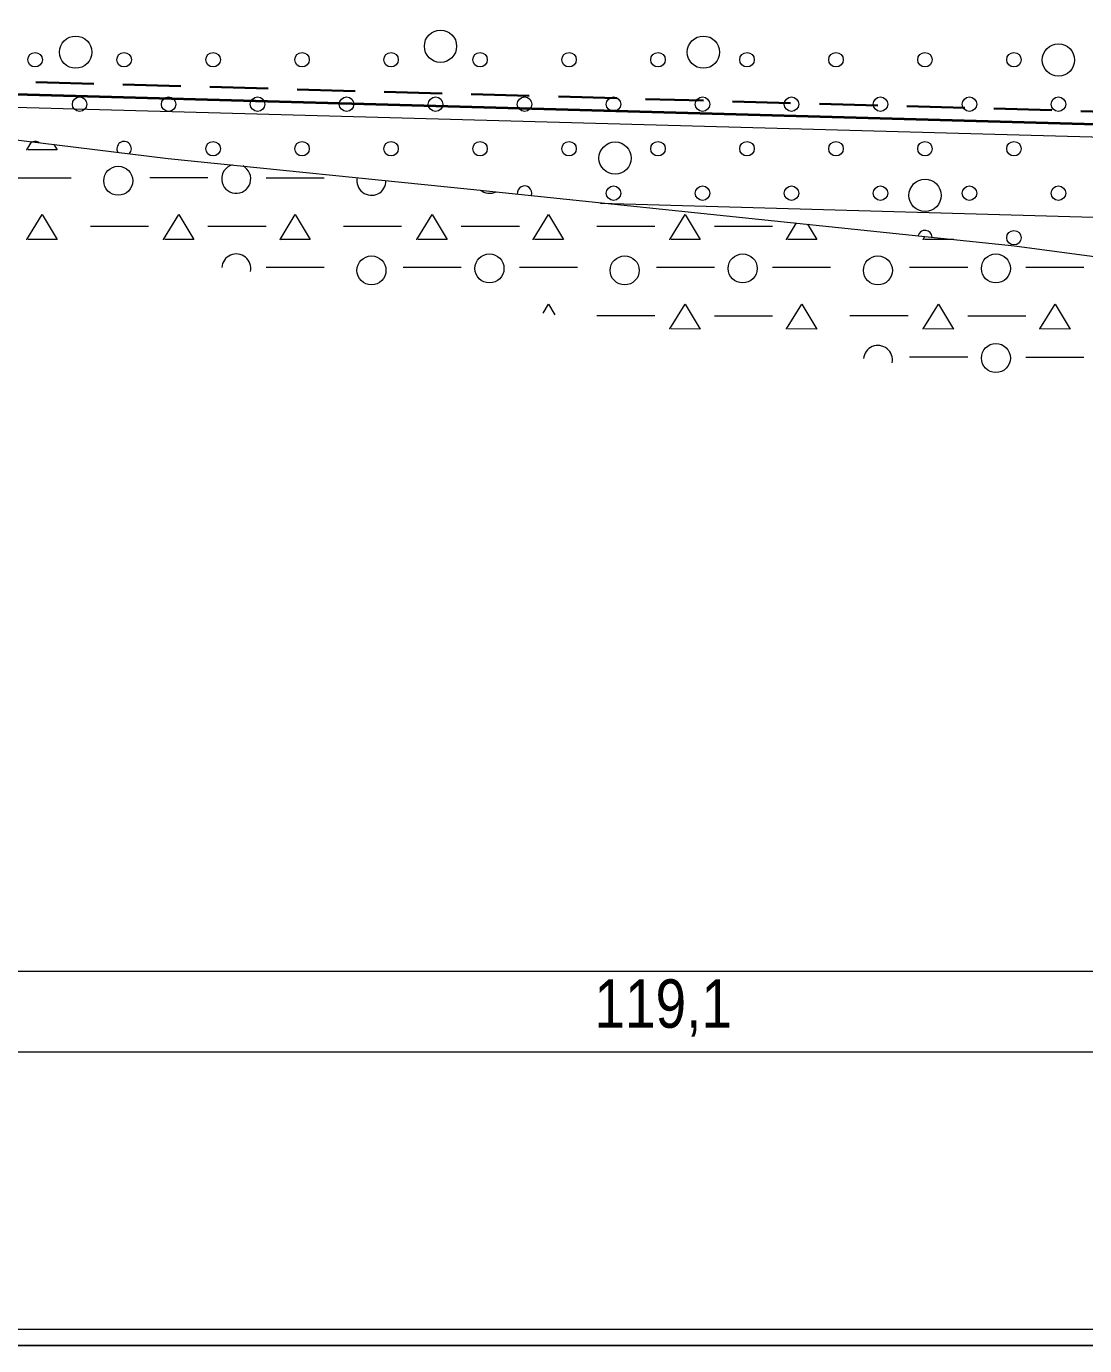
# Model space of a CAD drawing. Extents: x 640104 to 640970, y 6442278 to 6442689.
# Drawn here: x 640313.3 to 640378.9, y 6442282.5 to 6442364.3 of the extents above; entities that cross this region are included whole.
import ezdxf
from ezdxf.enums import TextEntityAlignment as Align

# ---------------------------------------------------------------- set-up
doc = ezdxf.new("R2010")
doc.units = 0
doc.header["$LTSCALE"] = 1.2
doc.linetypes.add('MEDIUM_DASHED', pattern=[4.5, 3, -1.5])
for name, color, linetype, lineweight in [('30', 7, 'Continuous', 13), ('31', 7, 'Continuous', 13), ('34', 7, 'Continuous', 25), ('35', 7, 'Continuous', 35), ('42', 7, 'Continuous', 13), ('46', 7, 'Continuous', 13), ('47', 7, 'Continuous', 13), ('50', 7, 'Continuous', 13)]:
    doc.layers.add(name, color=color, linetype=linetype, lineweight=lineweight)

msp = doc.modelspace()

# ---------------------------------------------------------------- linework, layer by layer
at = {"layer": '30'}
for p, q in [((640112.44, 6442305.75), (640578.08, 6442305.75)), ((640112.44, 6442300.75), (640578.08, 6442300.75))]:
    msp.add_line(p, q, dxfattribs=at)
at = {"layer": '31'}
msp.add_lwpolyline([(640139.08, 6442391.74), (640152, 6442391.74), (640184.83, 6442387.53), (640224.44, 6442383.27), (640230.93, 6442382.67), (640242.81, 6442381.6), (640246.59, 6442379.93), (640268.17, 6442370.27), (640295.32, 6442359.75), (640299.34, 6442358.9), (640322.09, 6442356.12), (640340.84, 6442354.22), (640374.54, 6442350.71), (640388.93, 6442348.78), (640409.14, 6442347), (640414.32, 6442346.47), (640439.11, 6442345.27), (640478.03, 6442341.77)], dxfattribs=at)
at = {"layer": '34', "lineweight": 13}
msp.add_lwpolyline([(640577.98, 6442339.23), (640519.43, 6442345.64), (640414.37, 6442351.46), (640348.88, 6442353.33)], dxfattribs=at)
at = {"layer": '35', "linetype": 'MEDIUM_DASHED'}
msp.add_lwpolyline([(640518.62, 6442352.3), (640414.65, 6442358.06), (640295.64, 6442361.35)], dxfattribs=at)
at = {"layer": '35', "lineweight": 40}
msp.add_lwpolyline([(640518.52, 6442351.5), (640414.61, 6442357.26), (640295.48, 6442360.55)], dxfattribs=at)
at = {"layer": '35', "lineweight": 13}
msp.add_lwpolyline([(640519.42, 6442350.65), (640414.58, 6442356.46), (640295.32, 6442359.75)], dxfattribs=at)
at = {"layer": '42'}
for centre in [(640313.846, 6442362.238), (640319.362, 6442362.238), (640324.877, 6442362.238), (640330.392, 6442362.238), (640335.908, 6442362.238), (640341.423, 6442362.238), (640346.939, 6442362.238), (640352.454, 6442362.238), (640357.97, 6442362.238), (640363.485, 6442362.238), (640369, 6442362.238), (640374.516, 6442362.238), (640316.604, 6442359.481), (640322.119, 6442359.481), (640327.635, 6442359.481), (640333.15, 6442359.481), (640338.666, 6442359.481), (640344.181, 6442359.481), (640349.696, 6442359.481), (640355.212, 6442359.481), (640360.727, 6442359.481), (640366.243, 6442359.481), (640371.758, 6442359.481), (640377.274, 6442359.481), (640324.877, 6442356.723), (640330.392, 6442356.723), (640335.908, 6442356.723), (640341.423, 6442356.723), (640346.939, 6442356.723), (640352.454, 6442356.723), (640357.97, 6442356.723), (640363.485, 6442356.723), (640369, 6442356.723), (640374.516, 6442356.723), (640349.696, 6442353.965), (640355.212, 6442353.965), (640360.727, 6442353.965), (640366.243, 6442353.965), (640371.758, 6442353.965), (640377.274, 6442353.965), (640374.516, 6442351.207)]:
    msp.add_circle(centre, 0.45, dxfattribs=at)
for centre, start, end in [((640313.846, 6442356.723), 57.02131, 109.04435), ((640319.362, 6442356.723), 317.01638, 209.04927), ((640344.181, 6442353.965), 342.57788, 185.5284), ((640369, 6442351.207), 4.54, 163.56627)]:
    msp.add_arc(centre, 0.45, start, end, dxfattribs=at)
at = {"layer": '46'}
for p, q in [((640316.07, 6442354.9), (640312.47, 6442354.9)), ((640324.56, 6442354.91), (640320.96, 6442354.91)), ((640331.76, 6442354.9), (640328.16, 6442354.9)), ((640320.87, 6442351.91), (640317.27, 6442351.91)), ((640328.16, 6442351.91), (640324.56, 6442351.91)), ((640336.56, 6442351.91), (640332.96, 6442351.91)), ((640343.86, 6442351.91), (640340.26, 6442351.91)), ((640352.26, 6442351.91), (640348.66, 6442351.91)), ((640359.55, 6442351.91), (640355.95, 6442351.91)), ((640331.76, 6442349.35), (640328.16, 6442349.35)), ((640340.26, 6442349.35), (640336.66, 6442349.35)), ((640347.46, 6442349.35), (640343.86, 6442349.35)), ((640355.95, 6442349.35), (640352.35, 6442349.35)), ((640363.15, 6442349.35), (640359.55, 6442349.35)), ((640371.65, 6442349.35), (640368.05, 6442349.35)), ((640378.85, 6442349.35), (640375.25, 6442349.35)), ((640352.26, 6442346.36), (640348.66, 6442346.36)), ((640359.55, 6442346.35), (640355.95, 6442346.35)), ((640367.95, 6442346.36), (640364.35, 6442346.36)), ((640375.25, 6442346.35), (640371.65, 6442346.35)), ((640371.65, 6442343.8), (640368.05, 6442343.8)), ((640378.85, 6442343.79), (640375.25, 6442343.79))]:
    msp.add_line(p, q, dxfattribs=at)
for points in [[(640313.33, 6442356.64), (640313.33, 6442356.66), (640313.64, 6442357.16)], [(640315, 6442356.99), (640315.21, 6442356.65), (640313.41, 6442356.66)], [(640313.33, 6442351.08), (640313.33, 6442351.1), (640314.28, 6442352.64), (640315.21, 6442351.09), (640313.41, 6442351.1)], [(640321.8, 6442351.08), (640321.8, 6442351.1), (640322.75, 6442352.64), (640323.68, 6442351.09), (640321.88, 6442351.1)], [(640329.02, 6442351.08), (640329.03, 6442351.1), (640329.97, 6442352.64), (640330.9, 6442351.09), (640329.1, 6442351.1)], [(640337.5, 6442351.08), (640337.5, 6442351.1), (640338.45, 6442352.64), (640339.38, 6442351.09), (640337.58, 6442351.1)], [(640344.72, 6442351.08), (640344.72, 6442351.1), (640345.67, 6442352.64), (640346.6, 6442351.09), (640344.8, 6442351.1)], [(640353.19, 6442351.08), (640353.19, 6442351.1), (640354.14, 6442352.64), (640355.07, 6442351.09), (640353.27, 6442351.1)], [(640360.41, 6442351.08), (640360.42, 6442351.1), (640361.04, 6442352.12)], [(640361.72, 6442352.05), (640362.29, 6442351.09), (640360.49, 6442351.1)], [(640368.89, 6442351.08), (640368.89, 6442351.1), (640369, 6442351.29)], [(640370.76, 6442351.11), (640370.77, 6442351.09), (640368.97, 6442351.1)], [(640345.33, 6442346.53), (640345.67, 6442347.08), (640346.06, 6442346.43)], [(640353.19, 6442345.53), (640353.19, 6442345.55), (640354.14, 6442347.08), (640355.07, 6442345.54), (640353.27, 6442345.55)], [(640360.41, 6442345.53), (640360.42, 6442345.55), (640361.36, 6442347.08), (640362.29, 6442345.54), (640360.49, 6442345.55)], [(640368.89, 6442345.53), (640368.89, 6442345.55), (640369.84, 6442347.08), (640370.77, 6442345.54), (640368.97, 6442345.55)], [(640376.11, 6442345.53), (640376.11, 6442345.55), (640377.06, 6442347.08), (640377.99, 6442345.54), (640376.19, 6442345.55)]]:
    msp.add_lwpolyline(points, dxfattribs=at)
for centre in [(640318.997, 6442354.735), (640334.693, 6442349.181), (640342.006, 6442349.303), (640350.388, 6442349.181), (640357.701, 6442349.303), (640366.083, 6442349.181), (640373.396, 6442349.303), (640373.396, 6442343.748)]:
    msp.add_circle(centre, 0.9, dxfattribs=at)
for centre, start, end in [((640326.31, 6442354.857), 106.34155, 62.08835), ((640334.693, 6442354.735), 167.17134, 1.25856), ((640342.006, 6442354.857), 230.65807, 297.4482), ((640326.31, 6442349.303), 347.76965, 176.04619), ((640366.083, 6442343.626), 349.13948, 174.67636)]:
    msp.add_arc(centre, 0.9, start, end, dxfattribs=at)
at = {"layer": '47'}
for centre in [(640316.358, 6442362.706), (640338.973, 6442363.071), (640355.267, 6442362.706), (640377.274, 6442362.22), (640349.795, 6442356.14), (640369.006, 6442353.83)]:
    msp.add_circle(centre, 1, dxfattribs=at)
at = {"layer": '50', "lineweight": 25}
msp.add_lwpolyline([(640103.56, 6442688.99), (640970.3, 6442688.99), (640970.3, 6442282.54), (640103.56, 6442282.54)], close=True, dxfattribs=at)
at = {"layer": '50'}
msp.add_lwpolyline([(640104.56, 6442687.99), (640969.3, 6442687.99), (640969.3, 6442283.54), (640104.56, 6442283.54)], close=True, dxfattribs=at)

# ---------------------------------------------------------------- texts
at = {"layer": '30', "width": 0.85}
msp.add_text('119,1', height=3, dxfattribs=at).set_placement((640352.775, 6442302.24), align=Align.CENTER)

doc.saveas('drawing.dxf')
